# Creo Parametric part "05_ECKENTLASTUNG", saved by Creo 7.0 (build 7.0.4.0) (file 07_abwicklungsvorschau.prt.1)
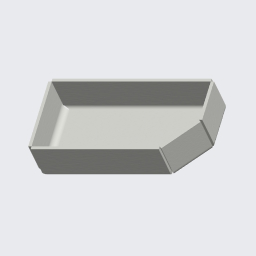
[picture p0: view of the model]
Units: millimeter Kilogram Sec (mmKs); MM, KILOGRAM, SECS
Materials in the file: S235JRG2

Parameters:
  PTC_MATERIAL_NAME = "S235JRG2"
  BENENNUNG = "XXX"
  DATUM = "XX.XX.XX"
  ERSTELLER = "ARINDA"
  TEILETYP = "Fertigungsteil"
  SMT_DFLT_BEND_REL_LENGTH_TYPE = "Through All"
  SELECT_EN_NAME = "S235JRG2"
  SELECT_DIN_NAME = "RSt37-2"
  SELECT_DIN_NUMBER = "1.0038"
  SELECT_ASTM_NAME = "A 283 M Grade 2"
  MATERIAL_GROUP = "ME_ST_Baustahl"
  STANDARD_EN_DELIVERYSPEC = "DIN EN 10025"
  STANDARD_DIN_DELIVERYSPEC = "DIN 17100"

Other parameters: MASSE, SMT_THICKNESS, SMT_PART_BEND_ALLOWANCE_FACTOR, SMT_DFLT_BEND_RADIUS, SMT_DFLT_BEND_ANGLE, SMT_DFLT_CRNR_REL_WIDTH, SMT_DFLT_CRNR_REL_DEPTH, SMT_DFLT_BEND_REL_WIDTH, SMT_DFLT_BEND_REL_DEPTH, SMT_DFLT_BEND_REL_LENGTH, SMT_DFLT_BEND_REL_ANGLE, SMT_GAP, SMT_DFLT_EDGE_TREA_WIDTH, SMT_DFLT_MITER_CUT_WIDTH, SMT_DFLT_MITER_CUT_OFFSET, D10, D18, SMT_FLAT_PATTERN_LENGTH

Created from: ARINDA-STARTTEIL.PRT

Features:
  1. coordinate system
  2. datum plane "T_RECHTS_Y-Z"
  3. datum plane "T_OBEN_X-Z"
  4. datum plane "T_VORNE_X-Y"
  5. datum axis "T_X-ACHSE"
  6. datum axis "A_1"
  7. datum axis "A_2"
  8. extrusion "Profil 1"
  9. feature "Konvertieren(Erste Lasche)"
  10. feature "Konvertierung 1"

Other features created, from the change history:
  chamfer "Fase 1"
  feature "Endabwicklung 1" (2 times)

Other named items: T_BASIC, T_Y-ACHSE, T_Z-ACHSE

Layers: 00_STD-ACHSEN, 00_STD-EBENEN, 00_STD-KOORDSYS, 01_ACHSEN, SAMMELFLÄCHEN, VOLUMENGEOMETRIE

Surfaces: 29 plane, 10 cylinder, 10 ruled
